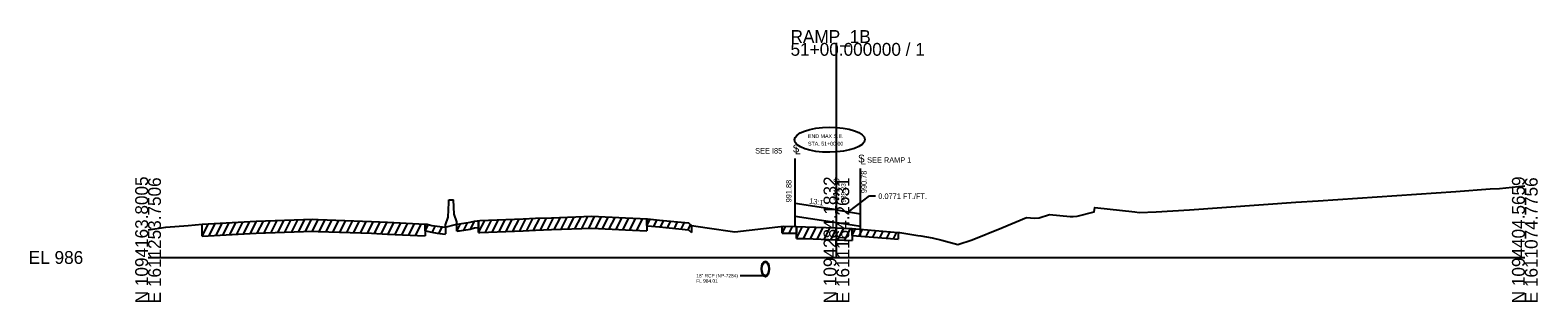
# Model space of a CAD drawing. Extents: x -26 to 1615461, y 490 to 1281970.
# Drawn here: x -25.7 to 302.8, y 990.3 to 1049.6 of the extents above; entities that cross this region are included whole.
import ezdxf

# ---------------------------------------------------------------- set-up
doc = ezdxf.new("R2010")
doc.units = 0
for name, color, linetype in [('RD_EX_Misc', 7, 'Continuous'), ('RD_GPK_XS_Cell', 7, 'Continuous'), ('RD_Sketch1', 7, 'Continuous'), ('RD_XE_Ground', 7, 'Continuous'), ('RD_XS_Base', 7, 'Continuous'), ('RD_XS_ExGround', 7, 'Continuous'), ('RD_XS_ExPaveRet', 7, 'Continuous'), ('RD_XS_MatchLine', 7, 'Continuous'), ('RD_XS_Pave', 7, 'Continuous'), ('RD_XS_PaveShd', 7, 'Continuous'), ('RD_XS_Pipe', 7, 'Continuous'), ('RD_XS_TX_Elev_EX', 7, 'Continuous'), ('RD_XS_TX_Elev_PR', 7, 'Continuous'), ('RD_XS_TX_MatchLine', 7, 'Continuous'), ('RD_XS_TX_Notes', 7, 'Continuous'), ('RD_XS_TX_ShdSlope', 7, 'Continuous'), ('RD_XS_TX_Slope', 7, 'Continuous')]:
    doc.layers.add(name, color=color, linetype=linetype)

msp = doc.modelspace()

# ---------------------------------------------------------------- linework, layer by layer
at = {"layer": 'RD_EX_Misc'}
for p, q in [((60.41, 1005.8), (60.41, 1007.3)), ((60.41, 1005.8), (60.83, 1005.78)), ((60.83, 1005.78), (61.81, 1005.5)), ((61.81, 1005.5), (63.01, 1005.34)), ((63.01, 1005.34), (64.71, 1005.12)), ((64.79, 1006.64), (64.79, 1005.14)), ((67.3, 1005.76), (67.3, 1007.26)), ((67.3, 1005.76), (67.43, 1005.79)), ((67.43, 1005.79), (67.84, 1005.82)), ((67.84, 1005.82), (70.16, 1006.19)), ((70.16, 1006.19), (71.13, 1006.46)), ((71.13, 1006.46), (72.01, 1006.53)), ((72.01, 1008.03), (72.01, 1006.53)), ((108.69, 1006.95), (108.69, 1008.45)), ((108.69, 1006.95), (108.85, 1006.94)), ((108.85, 1006.94), (111.48, 1006.68)), ((111.48, 1006.68), (117.76, 1006.04)), ((117.76, 1006.04), (118.39, 1005.49)), ((118.39, 1006.99), (118.39, 1005.49)), ((138.21, 1005.31), (138.21, 1006.81)), ((138.21, 1005.31), (138.43, 1005.33)), ((138.43, 1005.33), (141.33, 1005.28)), ((141.33, 1006.78), (141.33, 1005.28)), ((153.46, 1004.83), (153.46, 1006.33)), ((163.47, 1005.49), (163.47, 1003.99)), ((64.71, 1005.12), (64.79, 1005.14)), ((153.46, 1004.83), (161.76, 1004.13)), ((161.76, 1004.13), (163.47, 1003.99))]:
    msp.add_line(p, q, dxfattribs=at)
at = {"layer": 'RD_GPK_XS_Cell'}
for p, q in [((150, 1000), (150, 1046.83)), ((0, 1000), (150, 1000)), ((150, 1000), (300, 1000))]:
    msp.add_line(p, q, dxfattribs=at)
at = {"layer": 'RD_Sketch1'}
for p, q in [((60.41, 1005.8), (61.11, 1007.2)), ((61.91, 1005.48), (62.61, 1006.89)), ((63.41, 1005.28), (64.11, 1006.69)), ((67.3, 1005.76), (68.1, 1007.36)), ((68.8, 1005.97), (69.61, 1007.6)), ((70.3, 1006.23), (71.16, 1007.96)), ((108.69, 1006.95), (109.41, 1008.39)), ((110.19, 1006.81), (110.9, 1008.24)), ((111.69, 1006.66), (112.4, 1008.09)), ((113.19, 1006.51), (113.9, 1007.93)), ((114.69, 1006.35), (115.4, 1007.78)), ((116.19, 1006.2), (116.9, 1007.63)), ((117.69, 1006.05), (118.23, 1007.13)), ((138.21, 1005.31), (138.96, 1006.82)), ((139.71, 1005.3), (140.45, 1006.79)), ((153.46, 1004.83), (154.18, 1006.27)), ((154.96, 1004.7), (155.68, 1006.14)), ((156.46, 1004.58), (157.18, 1006.02)), ((157.96, 1004.45), (158.68, 1005.89)), ((159.46, 1004.32), (160.18, 1005.76)), ((160.96, 1004.2), (161.68, 1005.64)), ((162.46, 1004.07), (163.18, 1005.52))]:
    msp.add_line(p, q, dxfattribs=at)
at = {"layer": 'RD_XE_Ground'}
for p, q in [((65.37, 1008.8), (65.54, 1011.97)), ((65.54, 1012.59), (66.55, 1012.59)), ((65.54, 1011.97), (65.54, 1012.59)), ((66.71, 1009.42), (66.55, 1012.59)), ((64.79, 1007.14), (65.37, 1008.8)), ((67.3, 1007.76), (66.71, 1009.42)), ((64.79, 1006.64), (64.79, 1007.14)), ((67.3, 1007.26), (67.3, 1007.76))]:
    msp.add_line(p, q, dxfattribs=at)
at = {"layer": 'RD_XS_Base'}
for p, q in [((153.46, 1007.06), (141.03, 1008.97)), ((155.27, 1006.78), (153.46, 1007.06))]:
    msp.add_line(p, q, dxfattribs=at)
at = {"layer": 'RD_XS_ExGround'}
msp.add_lwpolyline([(0, 1006.01), (3.89, 1006.61), (8.77, 1007), (11.81, 1007.26), (16.99, 1007.53), (23.56, 1007.9), (33.85, 1008.27), (35.85, 1008.35), (37.09, 1008.3), (48.69, 1007.89), (52.2, 1007.71), (60.41, 1007.3), (60.83, 1007.28), (61.81, 1007), (63.01, 1006.84), (64.71, 1006.62), (67, 1007.18), (67.43, 1007.29), (67.84, 1007.32), (70.16, 1007.69), (71.13, 1007.96), (72.26, 1008.05), (81.72, 1008.44), (84.43, 1008.55), (87.93, 1008.68), (96.73, 1008.99), (104.01, 1008.67), (108.85, 1008.44), (111.48, 1008.18), (117.76, 1007.54), (118.39, 1006.99), (121.82, 1006.5), (127.85, 1005.61), (137.2, 1006.71), (138.43, 1006.83), (141.33, 1006.78), (143.24, 1006.71), (150, 1006.46), (153.46, 1006.33), (161.76, 1005.63), (163.47, 1005.49), (163.81, 1005.42), (167.76, 1004.79), (168.42, 1004.73), (170.88, 1004.28), (172.99, 1003.77), (176.46, 1002.82), (179.54, 1003.86), (186.07, 1006.5), (191.39, 1008.73), (193.17, 1008.57), (194.21, 1008.69), (196.43, 1009.4), (200.94, 1008.98), (201.6, 1008.92), (202.42, 1009.03), (206.19, 1009.98), (206.28, 1010.93), (215.02, 1009.93), (215.94, 1009.82), (219.64, 1009.97), (226.91, 1010.39), (250.12, 1012.06), (254.97, 1012.34), (284.94, 1014.42), (292.48, 1014.97), (294.45, 1015.08), (300, 1015.61)], dxfattribs=at)
at = {"layer": 'RD_XS_ExPaveRet'}
for p, q in [((85.51, 1005.99), (86.84, 1008.64)), ((87.01, 1006.04), (88.34, 1008.69)), ((88.51, 1006.1), (89.84, 1008.75)), ((90.01, 1006.15), (91.34, 1008.8)), ((91.51, 1006.2), (92.84, 1008.85)), ((93.01, 1006.26), (94.34, 1008.9)), ((94.51, 1006.31), (95.84, 1008.96)), ((96.01, 1006.36), (97.31, 1008.96)), ((97.51, 1006.35), (98.79, 1008.9)), ((99.01, 1006.29), (100.29, 1008.83)), ((100.51, 1006.22), (101.79, 1008.76)), ((102.01, 1006.15), (103.29, 1008.7)), ((103.51, 1006.09), (104.79, 1008.63)), ((11.81, 1004.66), (13.15, 1007.33)), ((11.81, 1004.66), (11.81, 1007.26)), ((13.31, 1004.74), (14.65, 1007.41)), ((14.81, 1004.81), (16.15, 1007.48)), ((16.31, 1004.89), (17.65, 1007.56)), ((17.81, 1004.97), (19.15, 1007.65)), ((19.31, 1005.06), (20.65, 1007.73)), ((20.81, 1005.14), (22.15, 1007.82)), ((22.31, 1005.23), (23.65, 1007.9)), ((23.56, 1005.3), (33.85, 1005.67)), ((23.81, 1005.31), (25.14, 1007.96)), ((25.31, 1005.36), (26.64, 1008.01)), ((26.81, 1005.42), (28.14, 1008.06)), ((28.31, 1005.47), (29.64, 1008.12)), ((29.81, 1005.52), (31.14, 1008.17)), ((31.31, 1005.58), (32.64, 1008.23)), ((32.81, 1005.63), (34.14, 1008.28)), ((33.85, 1005.67), (35.85, 1005.75)), ((34.31, 1005.69), (35.64, 1008.34)), ((35.81, 1005.74), (37.09, 1008.3)), ((35.85, 1005.75), (37.09, 1005.7)), ((37.09, 1005.7), (48.69, 1005.29)), ((37.31, 1005.69), (38.59, 1008.25)), ((38.81, 1005.64), (40.09, 1008.19)), ((40.31, 1005.59), (41.59, 1008.14)), ((41.81, 1005.53), (43.09, 1008.09)), ((43.31, 1005.48), (44.59, 1008.04)), ((44.81, 1005.43), (46.09, 1007.98)), ((46.31, 1005.37), (47.59, 1007.93)), ((47.81, 1005.32), (49.09, 1007.87)), ((49.31, 1005.26), (50.58, 1007.8)), ((50.81, 1005.18), (52.08, 1007.72)), ((52.31, 1005.11), (53.58, 1007.64)), ((53.81, 1005.03), (55.08, 1007.57)), ((55.31, 1004.95), (56.58, 1007.49)), ((56.81, 1004.88), (58.08, 1007.41)), ((58.31, 1004.8), (59.58, 1007.34)), ((60.41, 1007.3), (60.41, 1004.7)), ((72.01, 1005.43), (73.35, 1008.09)), ((72.01, 1005.43), (72.01, 1008.03)), ((72.01, 1005.43), (72.26, 1005.45)), ((72.26, 1005.45), (81.72, 1005.84)), ((73.51, 1005.5), (74.84, 1008.15)), ((75.01, 1005.56), (76.34, 1008.22)), ((76.51, 1005.62), (77.84, 1008.28)), ((78.01, 1005.69), (79.34, 1008.34)), ((79.51, 1005.75), (80.84, 1008.4)), ((81.01, 1005.81), (82.34, 1008.46)), ((81.72, 1005.84), (84.43, 1005.95)), ((82.51, 1005.87), (83.84, 1008.52)), ((84.01, 1005.93), (85.34, 1008.58)), ((84.43, 1005.95), (87.93, 1006.08)), ((87.93, 1006.08), (96.73, 1006.39)), ((96.73, 1006.39), (104.01, 1006.07)), ((104.01, 1006.07), (108.69, 1005.85)), ((105.01, 1006.02), (106.28, 1008.56)), ((106.51, 1005.95), (107.78, 1008.49)), ((108.69, 1008.45), (108.69, 1005.85)), ((141.33, 1004.18), (141.33, 1006.78)), ((141.33, 1004.18), (142.6, 1006.73)), ((142.83, 1004.12), (144.1, 1006.68)), ((144.33, 1004.07), (145.6, 1006.62)), ((145.83, 1004.01), (147.1, 1006.56)), ((147.33, 1003.96), (148.6, 1006.51)), ((148.83, 1003.9), (150.1, 1006.45)), ((150.33, 1003.84), (151.6, 1006.4)), ((151.83, 1003.79), (153.1, 1006.34)), ((153.46, 1006.33), (153.46, 1003.73)), ((11.81, 1004.66), (16.99, 1004.93)), ((16.99, 1004.93), (23.56, 1005.3)), ((48.69, 1005.29), (52.2, 1005.11)), ((52.2, 1005.11), (60.41, 1004.7)), ((141.33, 1004.18), (143.24, 1004.11)), ((143.24, 1004.11), (150, 1003.86)), ((150, 1003.86), (153.46, 1003.73))]:
    msp.add_line(p, q, dxfattribs=at)
at = {"layer": 'RD_XS_MatchLine'}
for p, q in [((141.03, 1006.79), (141.03, 1011.75)), ((155.27, 1006.18), (155.27, 1009.55))]:
    msp.add_line(p, q, dxfattribs=at)
at = {"layer": 'RD_XS_Pave'}
msp.add_line((150, 1010.37), (155.27, 1009.55), dxfattribs=at)
at = {"layer": 'RD_XS_PaveShd'}
msp.add_line((150, 1010.37), (141.03, 1011.75), dxfattribs=at)
at = {"layer": 'RD_XS_Pipe'}
msp.add_line((134.02, 996.01), (129.02, 996.01), dxfattribs=at)
for major_axis in [(0, 1.7), (0, 1.5)]:
    msp.add_ellipse((134.52, 997.51), major_axis=major_axis, ratio=0.5, dxfattribs=at)
at = {"layer": 'RD_XS_TX_Elev_PR'}
for p, q in [((152.64, 1009.96), (157.2, 1013.47)), ((157.2, 1013.47), (158.51, 1013.47))]:
    msp.add_line(p, q, dxfattribs=at)
at = {"layer": 'RD_XS_TX_MatchLine'}
for p, q in [((141.03, 1011.75), (141.03, 1021.64)), ((155.27, 1009.55), (155.27, 1019.44)), ((141.03, 1006.75), (141.03, 1011.75)), ((155.27, 1004.55), (155.27, 1009.55))]:
    msp.add_line(p, q, dxfattribs=at)
at = {"layer": 'RD_XS_TX_Notes'}
msp.add_ellipse((148.51, 1025.7), major_axis=(7.68, 0.05), ratio=0.355189, dxfattribs=at)

# ---------------------------------------------------------------- texts
at = {"layer": 'RD_GPK_XS_Cell'}
for s, p in [('RAMP_1B', (140, 1046.83)), ('51+00.000000 / 1', (140, 1044.03)), ('EL 986', (-26, 998.6))]:
    msp.add_text(s, height=2.8, dxfattribs=at).set_placement(p)
for s, p in [('N 1094163.8005', (0, 990)), ('E 1611253.7506', (2.8, 990)), ('N 1094284.1832', (150, 990)), ('E 1611164.2631', (152.8, 990)), ('N 1094404.5659', (300, 990)), ('E 1611074.7756', (302.8, 990))]:
    msp.add_text(s, height=2.8, rotation=90, dxfattribs=at).set_placement(p)
at = {"layer": 'RD_XS_Pipe'}
for s, p in [('18" RCP (NP-7284)', (119.47, 995.64)), ('FL 984.01', (119.47, 994.51))]:
    msp.add_text(s, height=0.75, dxfattribs=at).set_placement(p)
at = {"layer": 'RD_XS_TX_Elev_EX'}
msp.add_text('989.23', height=1, rotation=90, dxfattribs=at).set_placement((152, 1011.99))
at = {"layer": 'RD_XS_TX_Elev_PR'}
for s, p in [('990.78', (156.59, 1014.04)), ('991.88', (140.2, 1012.04)), ('991.18', (150.6, 1012.37))]:
    msp.add_text(s, height=1.2, rotation=90, dxfattribs=at).set_placement(p)
at = {"layer": 'RD_XS_TX_MatchLine'}
for s, p in [('S', (140.44, 1022.95)), ('L', (140.96, 1022.52)), ('S', (154.69, 1020.76)), ('L', (155.21, 1020.32))]:
    msp.add_text(s, height=1.68, dxfattribs=at).set_placement(p)
at = {"layer": 'RD_XS_TX_Notes'}
for s, p in [('STA. 51+00.00', (143.8, 1024.42)), ('END MAX S.E. ', (143.8, 1026.08))]:
    msp.add_text(s, height=0.8333, dxfattribs=at).set_placement(p)
for s, p in [('SEE I85', (132.29, 1022.69)), ('SEE RAMP 1', (156.69, 1020.68))]:
    msp.add_text(s, height=1.2, rotation=360, dxfattribs=at).set_placement(p)
at = {"layer": 'RD_XS_TX_ShdSlope'}
msp.add_text('13:1', height=1.2, rotation=351.229, dxfattribs=at).set_placement((144, 1011.8))
msp.add_text('13:1', height=1.2, rotation=351.229, dxfattribs=at).set_placement((144, 1011.8))
at = {"layer": 'RD_XS_TX_Slope'}
msp.add_text('0.0771 FT./FT.', height=1.2, dxfattribs=at).set_placement((159.13, 1012.78))

doc.saveas('drawing.dxf')
